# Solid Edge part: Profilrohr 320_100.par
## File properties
Username: ahadarics
Dokumentum tartalom típus: 0
Author: ahadarics
Last saved by: ahadarics
Revision: 81
Sűrűség: 0,000 kg/m^3
Pontosság: 0,990
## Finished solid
Body 1: solid body, 4 faces, 6 edges, 4 vertices.
  Faces by surface: cylinder 2, plane 2
  Edges by curve: circle 4, line 2
Bounding box of the edges (mm): 336.000 x 336.000 x 190.000, from (-168, -168, -132.5) to (168, 168, 57.5).
Cylindrical faces by radius (mm): R160 x1, R168 x1
Planar faces by outward normal: +z 1, -z 1
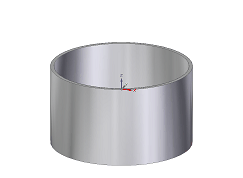
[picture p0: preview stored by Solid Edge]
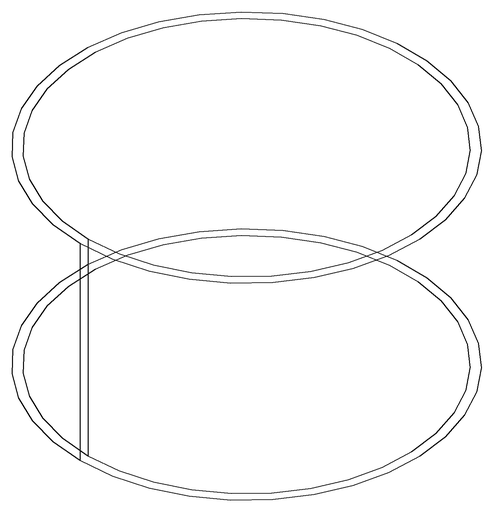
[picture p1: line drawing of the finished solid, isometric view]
